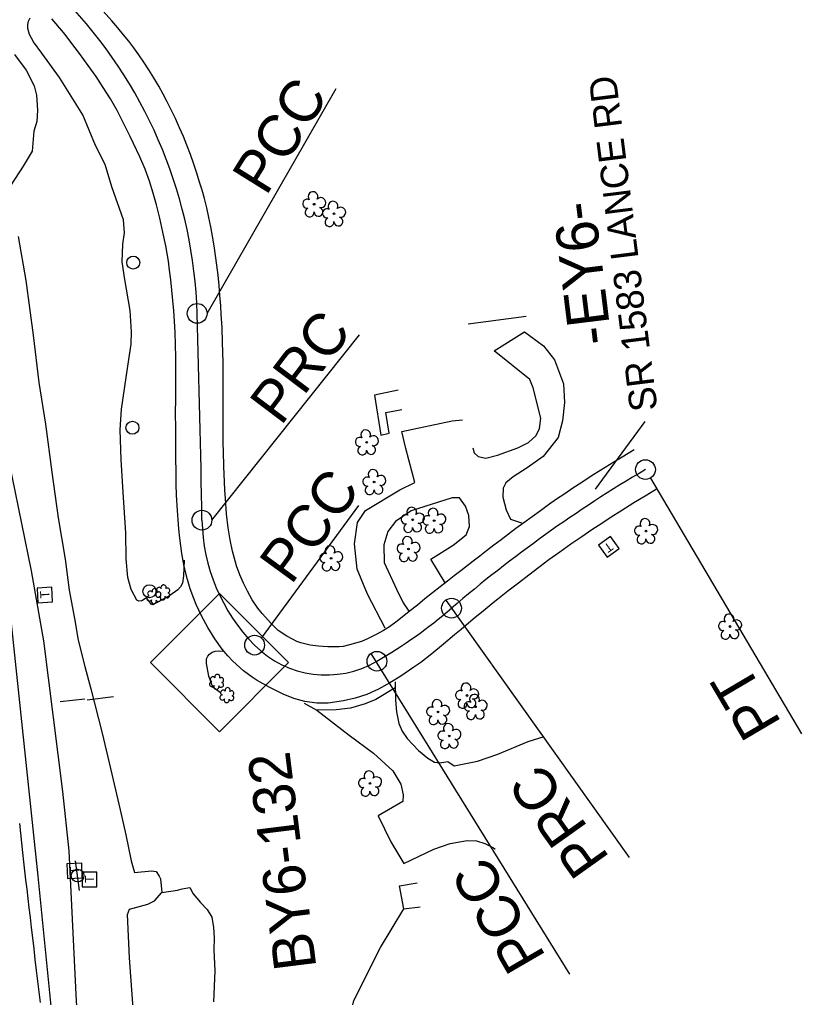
# Model space of a CAD drawing. Extents: x 476627 to 479509, y 495837 to 499842.
# Drawn here: x 478160.5 to 478457.3, y 497245.6 to 497616.9 of the extents above; entities that cross this region are included whole.
import ezdxf

# ---------------------------------------------------------------- set-up
doc = ezdxf.new("R2010")
doc.units = 0
for name, color, linetype in [('CTL Secondary Horizontal and Vertical CELL', 7, 'Continuous'), ('CTL Secondary Horizontal and Vertical Text', 7, 'Continuous'), ('Exist Horizontal Alignment', 7, 'Continuous'), ('Exist Horizontal Alignment Direction Label', 7, 'Continuous'), ('Exist Other Culture Area Outline', 7, 'Continuous'), ('Exist Other Culture Fence Line', 7, 'Continuous'), ('Exist Other Culture Sign', 7, 'Continuous'), ('Exist Roads Change in Surface', 7, 'Continuous'), ('Exist Roads EOP', 7, 'Continuous'), ('Exist Roads EOP Leader', 7, 'Continuous'), ('Exist Roads EOP Other', 7, 'Continuous'), ('Exist Roads EOP Text', 7, 'Continuous'), ('Exist Roads Soil', 7, 'Continuous'), ('Exist Utilities Other Pole CELL', 7, 'Continuous'), ('Exist Utilities Telephone Pedestal CELL', 7, 'Continuous'), ('Exist Utilities Telephone Pole CELL', 7, 'Continuous'), ('Exist Vegetation Hedge Row', 7, 'Continuous'), ('Exist Vegetation Shrub CELL', 7, 'Continuous'), ('Exist Vegetation Tree CELL', 7, 'Continuous'), ('Exist Vegetation Woods Line', 7, 'Continuous')]:
    doc.layers.add(name, color=color, linetype=linetype)

msp = doc.modelspace()

# ---------------------------------------------------------------- linework, layer by layer
at = {"layer": 'CTL Secondary Horizontal and Vertical CELL'}
msp.add_line((478236.26, 497372.67), (478236.26, 497372.67), dxfattribs=at)
msp.add_lwpolyline([(478210.19, 497372.76), (478236.4, 497398.97), (478262.65, 497372.72), (478236.44, 497346.51)], close=True, dxfattribs=at)
at = {"layer": 'Exist Horizontal Alignment'}
for p, q in [((478231.67, 497505.32), (478280.69, 497590.74)), ((478233.5, 497426.81), (478289.48, 497497.25)), ((478399.98, 497442.81), (478457.27, 497345.73)), ((478252.4, 497382), (478289.29, 497432.37)), ((478322.28, 497396.46), (478391.92, 497298.69)), ((478293.89, 497376.24), (478369.22, 497254.38))]:
    msp.add_line(p, q, dxfattribs=at)
for centre in [(478227.92, 497505.32), (478398.07, 497446.04), (478229.75, 497426.81), (478324.46, 497393.4), (478249.74, 497379.37), (478296.17, 497373.26)]:
    msp.add_circle(centre, 3.75, dxfattribs=at)
for centre, radius, start, end in [((478049.09, 497499.96), 178.91, 1.7193, 42.703), ((472276.25, 497326.67), 5954.35, 0.96365, 1.719327), ((478660.76, 497000.88), 516.89, 120.545, 130.5894), ((478298.83, 497427.98), 69.09, 180.9636, 224.7163), ((478198.36, 497540.58), 193.81, 300.3104, 310.5894), ((478276.89, 497406.25), 38.21, 224.7163, 300.3104)]:
    msp.add_arc(centre, radius, start, end, dxfattribs=at)
at = {"layer": 'Exist Other Culture Area Outline'}
msp.add_lwpolyline([(478304.26, 497476.19), (478295.26, 497474.27), (478297.62, 497459.04), (478300.85, 497459.8), (478299.55, 497467.66), (478305.58, 497468.87)], dxfattribs=at)
at = {"layer": 'Exist Other Culture Fence Line'}
msp.add_lwpolyline([(478330.72, 497501.4), (478352.74, 497504.27)], dxfattribs=at)
at = {"layer": 'Exist Other Culture Sign'}
for p, q in [((478185.28, 497358.89), (478175.93, 497357.87)), ((478196.2, 497359.72), (478186.14, 497358.48))]:
    msp.add_line(p, q, dxfattribs=at)
at = {"layer": 'Exist Roads Change in Surface'}
msp.add_lwpolyline([(478303.11, 497363.12), (478295.78, 497358.73), (478291.69, 497357.04), (478286.18, 497355.42), (478280.68, 497354.79), (478273.3, 497354.64)], dxfattribs=at)
at = {"layer": 'Exist Roads EOP'}
for points in [[(478393.82, 497453.5), (478389.2, 497450.74), (478386.12, 497448.87), (478381.17, 497445.83), (478377.52, 497443.52), (478373.88, 497441.16), (478370.55, 497438.97), (478367.41, 497436.87), (478364.36, 497434.78), (478361.3, 497432.65), (478358.18, 497430.42), (478355.03, 497428.13), (478351.92, 497425.84), (478348.91, 497423.62), (478346.08, 497421.49), (478343.32, 497419.41), (478340.53, 497417.29), (478337.78, 497415.2), (478335.15, 497413.19), (478332.64, 497411.26), (478327.95, 497407.6), (478325.5, 497405.71), (478322.9, 497403.69), (478320.1, 497401.47), (478317.22, 497399.18), (478314.38, 497396.92), (478311.49, 497394.6), (478308.44, 497392.14), (478303.79, 497388.41), (478300.91, 497386.29), (478298.64, 497384.87), (478296.15, 497383.55), (478292.8, 497381.9), (478290.27, 497380.8), (478285.8, 497379.42), (478283.34, 497378.89), (478281.77, 497378.72), (478277.54, 497378.7), (478274.02, 497378.94), (478270.86, 497379.34), (478267.33, 497380.24), (478265.77, 497380.79), (478264.09, 497381.59), (478261.93, 497382.8), (478258.72, 497384.88), (478256.15, 497387.4), (478252.56, 497391.4), (478250.93, 497393.38), (478248.74, 497396.6), (478246.97, 497399.81), (478245.45, 497402.96), (478244.12, 497406.06), (478242.91, 497409.43), (478241.38, 497415.11), (478240.48, 497419.3), (478239.7, 497423.97), (478239.1, 497429.17), (478238.66, 497435.07), (478238.46, 497438.27), (478238.28, 497441.41), (478238.05, 497447.17), (478237.9, 497452.89), (478237.82, 497456.03), (478237.78, 497459.33), (478237.76, 497462.81), (478237.79, 497466.51), (478237.83, 497472.45), (478237.82, 497476.6), (478237.79, 497480.7), (478237.73, 497486.69), (478237.67, 497490.61), (478237.6, 497494.24), (478237.4, 497499.96), (478237.07, 497504.85), (478236.85, 497508.24), (478236.58, 497512.07), (478236.25, 497515.96), (478235.87, 497519.84), (478235.43, 497523.61), (478234.93, 497527.33), (478234.38, 497531.03), (478233.77, 497534.67), (478233.12, 497538.18), (478232.39, 497541.7), (478231.54, 497545.35), (478230.65, 497548.9), (478229.79, 497552.1), (478228.87, 497555.22), (478227.81, 497558.54), (478226.64, 497562.04), (478225.36, 497565.66), (478224.04, 497569.23), (478222.7, 497572.52), (478221.27, 497575.8), (478219.66, 497579.28), (478218.05, 497582.68), (478216.57, 497585.67), (478215.07, 497588.56), (478213.35, 497591.67), (478211.51, 497594.81), (478209.63, 497597.8), (478207.72, 497600.67), (478205.79, 497603.48), (478203.87, 497606.16), (478201.96, 497608.67), (478199.96, 497611.16), (478197.76, 497613.81), (478195.57, 497616.38), (478192.3, 497620.11)], [(478402.32, 497438.59), (478398.56, 497436.33), (478393.64, 497433.34), (478388.7, 497430.29), (478385.06, 497427.98), (478381.45, 497425.6), (478377.75, 497423.11), (478373.86, 497420.49), (478369.8, 497417.7), (478365.59, 497414.73), (478361.45, 497411.73), (478357.6, 497408.85), (478353.82, 497405.97), (478349.84, 497402.93), (478345.86, 497399.84), (478342.07, 497396.81), (478340.29, 497395.37), (478337.2, 497392.87), (478332.69, 497389.22), (478328.11, 497385.36), (478325.6, 497383.23), (478321.43, 497379.72), (478317, 497376.07), (478312.78, 497372.83), (478310.15, 497370.94), (478305.26, 497367.59), (478301.05, 497364.99), (478296.69, 497362.64), (478292.3, 497360.68), (478287.89, 497359.22), (478283.44, 497358.19), (478277.66, 497357.37), (478273.3, 497357.37), (478268.83, 497357.93), (478264.67, 497359.06), (478260.53, 497360.71), (478255.5, 497363.23), (478250.73, 497365.98), (478248.75, 497367.25), (478245.55, 497369.56), (478241.46, 497373.28), (478239.54, 497375.3), (478237.45, 497377.87), (478234.65, 497381.78), (478231.97, 497386.09), (478229.57, 497390.55), (478227.57, 497394.84), (478226.68, 497397.05), (478225.31, 497400.71), (478224.2, 497404.32), (478223.01, 497409.21), (478222.11, 497414.13), (478221.37, 497419.96), (478221, 497423.51), (478220.69, 497426.95), (478220.44, 497430.47), (478220.14, 497436.29), (478220, 497440.55), (478219.92, 497445.17), (478219.86, 497450.3), (478219.82, 497455.93), (478219.79, 497461.67), (478219.76, 497467.43), (478219.79, 497472.95), (478219.86, 497478.23), (478219.87, 497483.44), (478219.8, 497488.57), (478219.69, 497493.46), (478219.54, 497498.07), (478219.32, 497502.35), (478219.02, 497506.33), (478218.67, 497510.26), (478218.28, 497514.18), (478217.87, 497518.04), (478217.44, 497521.79), (478216.99, 497525.17), (478216.01, 497530.95), (478214.93, 497536.21), (478213.7, 497541.55), (478212.45, 497546.61), (478211.17, 497551.04), (478209.77, 497555.5), (478208.15, 497560.06), (478206.17, 497564.72), (478203.82, 497569.81), (478202.5, 497572.54), (478199.87, 497577.86), (478197.52, 497582.4), (478195, 497586.77), (478192.28, 497591.12), (478189.58, 497595.24), (478186.55, 497599.5), (478183.21, 497604), (478179.98, 497608.31), (478177.8, 497611.18), (478174.34, 497615.4), (478172.82, 497617.23)], [(478160.43, 497311.6), (478160.83, 497307.97), (478161.24, 497304.24), (478161.64, 497300.61), (478162.04, 497297.07), (478162.43, 497293.63), (478162.82, 497290.21), (478163.22, 497286.73), (478163.63, 497283.2), (478164.05, 497279.62), (478164.48, 497275.94), (478164.93, 497272.12), (478165.4, 497268.18), (478165.88, 497264.11), (478166.37, 497259.97), (478166.86, 497255.86), (478167.34, 497251.77), (478167.81, 497247.69), (478168.29, 497243.63)]]:
    msp.add_lwpolyline(points, dxfattribs=at)
at = {"layer": 'Exist Roads EOP Leader'}
msp.add_line((478379.15, 497438.63), (478397.9, 497464.22), dxfattribs=at)
at = {"layer": 'Exist Roads EOP Other'}
for points in [[(478222.93, 497411.63), (478222.68, 497405.72), (478222.36, 497402.94), (478221.66, 497401.5), (478220.57, 497400.41), (478217.52, 497398.26), (478211.09, 497394.64), (478210.56, 497394.8), (478208.65, 497397.29), (478206.98, 497396.24), (478205.78, 497396.02), (478205.05, 497396.39), (478202.91, 497400.49), (478201.59, 497405.04), (478201.01, 497412.18), (478200.79, 497422.07), (478199.82, 497437.28), (478199.08, 497449.8), (478198.76, 497461.08), (478199.22, 497468.97), (478201.66, 497485.25), (478202.82, 497493.61), (478202.97, 497498.33), (478202.44, 497506.49), (478200.53, 497518.23), (478199.48, 497524.91), (478199.69, 497531.57), (478200.29, 497535.86), (478200, 497540.89), (478195.54, 497553.4), (478192.97, 497561.85), (478189.33, 497569.13), (478184.48, 497580.67), (478175.67, 497594.94), (478169.03, 497604.12), (478165.76, 497608.41), (478164.3, 497611.2), (478163.68, 497613.49), (478163.6, 497614.97), (478163.88, 497616.28), (478164.6, 497617.61)], [(478158.58, 497603.6), (478163.02, 497597.72), (478166, 497591.76), (478167, 497588.13), (478167.37, 497582.54), (478167.08, 497578.21), (478165.96, 497574.54), (478165.31, 497566.92), (478161.85, 497561.27), (478157.25, 497553.99)], [(478159.97, 497534.58), (478162.89, 497517.88), (478165.68, 497497.05), (478167.84, 497479.11), (478170.36, 497463.26), (478172.76, 497445.1), (478175.16, 497427.69), (478177.82, 497412.02), (478179.39, 497400.26), (478181.42, 497389.44), (478182.81, 497381.27), (478185.26, 497371.23), (478187.57, 497362.81), (478191.86, 497345.91), (478195.51, 497330.36), (478198.74, 497316.77), (478200.79, 497307.33), (478202.83, 497297.44), (478204.09, 497293), (478210.61, 497293.7), (478212.34, 497293.36), (478213.54, 497291.67), (478214.02, 497290.57), (478214.52, 497285.39), (478220.43, 497286.38), (478222.27, 497286.78), (478225.14, 497287.4), (478226.36, 497284.94), (478229.16, 497281.61), (478231.67, 497279.04), (478233.53, 497276.02), (478234.13, 497272.18), (478234.37, 497268.18), (478234.29, 497263.69), (478234.58, 497255.76), (478234.09, 497243.91)], [(478236.81, 497361.26), (478233.85, 497363.41), (478232.33, 497367.62), (478231.51, 497372.36), (478231.5, 497374.22), (478231.99, 497375.14), (478232.63, 497375.91), (478233.6, 497376.69), (478234.75, 497377.06), (478235.95, 497377.21), (478237.68, 497377.12)], [(478303.04, 497365.39), (478303.26, 497358.53), (478303.63, 497354.09), (478304.42, 497349.58), (478305.75, 497346.73), (478307.66, 497343.97), (478311.95, 497339.39), (478315.45, 497336.46), (478318.06, 497334.88), (478320.02, 497334.63), (478323.01, 497335.12), (478325.41, 497333.54), (478334.36, 497335.29), (478342.05, 497337.92), (478353.52, 497342.84), (478359.65, 497344.63)], [(478268.5, 497357.36), (478273.3, 497354.64), (478285.57, 497345.16), (478294.91, 497338.38), (478302.24, 497331.68), (478305.19, 497326.53), (478306.15, 497322.49), (478306.02, 497319.96), (478296.65, 497314.5), (478301.4, 497304.7), (478306.35, 497296.41), (478317.7, 497301.86), (478324.01, 497304.07), (478330.4, 497305.18), (478333.88, 497305.06), (478337.05, 497304), (478340.36, 497302.46), (478341.03, 497301.86)]]:
    msp.add_lwpolyline(points, dxfattribs=at)
at = {"layer": 'Exist Roads Soil'}
for points in [[(478332.59, 497454.26), (478333, 497452.35), (478334.6, 497451.03), (478337.54, 497450.37), (478341.93, 497451.44), (478349.57, 497454.29), (478353.66, 497456.25), (478356.59, 497458.91), (478357.83, 497461.67), (478358.3, 497465.52), (478355.42, 497477.07), (478354.13, 497480.29), (478340.61, 497491.08), (478352.22, 497498.35), (478359.43, 497493.03), (478363.5, 497487.74), (478366.91, 497478.62), (478367.39, 497471.48), (478366.53, 497464.52), (478364.89, 497458.16), (478359.27, 497450.94), (478353.14, 497446.63), (478347.81, 497443.28), (478345.09, 497441.02), (478344.1, 497439.02), (478343.98, 497435.49), (478345.26, 497430.72), (478346.85, 497427.21), (478351.39, 497425.72)], [(478299.25, 497385.83), (478292.59, 497398.7), (478288.68, 497408.19), (478287.58, 497417.87), (478288.73, 497425.96), (478291.8, 497430.43), (478304.8, 497438.37), (478310.49, 497441.15), (478307.1, 497454.02), (478305.63, 497460.47), (478324.66, 497464.49), (478328.63, 497464.89)], [(478322.11, 497403.06), (478316.61, 497411.96), (478325.07, 497417.31), (478329.97, 497421.23), (478331.23, 497424.47), (478331.06, 497428.54), (478329.8, 497432.12), (478327.49, 497435.36), (478324.71, 497435.29), (478309.14, 497430.42), (478303.16, 497426.26), (478300.28, 497422.55), (478298.73, 497417.4), (478298.92, 497410.79), (478303.64, 497400.59), (478306.14, 497395.37), (478308.25, 497392.27)], [(478232.9, 497234.19), (478229.08, 497241.38), (478227.08, 497242.13), (478203.69, 497241.5), (478202.19, 497260.65), (478201.46, 497277.13), (478202.27, 497279.15), (478209.18, 497280.95), (478211.76, 497282.22), (478214.52, 497285.39)]]:
    msp.add_lwpolyline(points, dxfattribs=at)
at = {"layer": 'Exist Utilities Other Pole CELL'}
for centre in [(478203.66, 497524.61), (478203.37, 497461.91), (478209.82, 497399.83)]:
    msp.add_circle(centre, 2.46, dxfattribs=at)
at = {"layer": 'Exist Utilities Telephone Pedestal CELL'}
for p, q in [((478384.27, 497416.67), (478384.27, 497416.67)), ((478170.09, 497398.3), (478170.09, 497398.3)), ((478181.4, 497293.6), (478181.4, 497293.6)), ((478187.04, 497290.26), (478187.04, 497290.26))]:
    msp.add_line(p, q, dxfattribs=at)
for points in [[(478384.85, 497420.56), (478380.29, 497417.31), (478383.54, 497412.75), (478388.09, 497416), (478384.85, 497420.56)], [(478173.08, 497395.76), (478172.72, 497401.34), (478167.14, 497400.99), (478167.5, 497395.41), (478173.08, 497395.76)], [(478184.32, 497290.98), (478184.11, 497296.57), (478178.52, 497296.36), (478178.73, 497290.77), (478184.32, 497290.98)], [(478189.86, 497287.54), (478189.86, 497293.13), (478184.27, 497293.13), (478184.27, 497287.54), (478189.86, 497287.54)]]:
    msp.add_lwpolyline(points, dxfattribs=at)
at = {"layer": 'Exist Utilities Telephone Pole CELL'}
for p, q in [((478183.31, 497286.24), (478181.79, 497297.48)), ((478182.55, 497291.87), (478182.55, 497291.87))]:
    msp.add_line(p, q, dxfattribs=at)
msp.add_circle((478182.55, 497291.87), 2.41, dxfattribs=at)
at = {"layer": 'Exist Vegetation Hedge Row'}
for points in [[(478190.09, 497080.94), (478179.04, 497176.49), (478167.62, 497291.69), (478149.68, 497459.52), (478153.94, 497461.52), (478164.92, 497407.53), (478169.64, 497380.94), (478176.79, 497323.8), (478179.27, 497301.23), (478182, 497244.2), (478186.73, 497178.82), (478185.59, 497158.67), (478193.35, 497075.53), (478190.09, 497080.94)], [(478306.34, 497279.2), (478304.78, 497288.01), (478311.4, 497289.14)]]:
    msp.add_lwpolyline(points, dxfattribs=at)
at = {"layer": 'Exist Vegetation Shrub CELL'}
for p, q in [((478211.59, 497397.78), (478211.59, 497397.78)), ((478214.95, 497399.22), (478214.95, 497399.22)), ((478235.36, 497365.23), (478235.36, 497365.23)), ((478239.25, 497360.2), (478239.25, 497360.2))]:
    msp.add_line(p, q, dxfattribs=at)
for centre, radius, start, end in [((478210.1, 497398.9), 0.968, 35.8908, 245.4216), ((478211.81, 497399.82), 0.99, 334.8391, 200.4717), ((478213.47, 497400.35), 0.968, 35.8908, 245.4216), ((478215.18, 497401.26), 0.99, 334.8391, 200.4717), ((478216.63, 497400.09), 0.929, 284.4567, 126.0861), ((478209.79, 497397.07), 0.955, 95.1099, 327.9534), ((478211.46, 497396.09), 0.984, 151.2797, 21.387), ((478213.15, 497398.52), 0.955, 95.1099, 327.9534), ((478213.22, 497396.85), 0.937, 204.9913, 73.4601), ((478213.26, 497398.65), 0.929, 284.4567, 126.0861), ((478214.83, 497397.54), 0.984, 151.2797, 21.387), ((478216.59, 497398.29), 0.937, 204.9913, 73.4601), ((478233.88, 497366.36), 0.968, 35.8908, 245.4216), ((478235.59, 497367.27), 0.99, 334.8391, 200.4717), ((478237.04, 497366.1), 0.929, 284.4567, 126.0861), ((478233.56, 497364.53), 0.955, 95.1099, 327.9534), ((478235.24, 497363.55), 0.984, 151.2797, 21.387), ((478237, 497364.3), 0.937, 204.9913, 73.4601), ((478239.48, 497362.24), 0.99, 334.8391, 200.4717), ((478237.45, 497359.49), 0.955, 95.1099, 327.9534), ((478237.77, 497361.32), 0.968, 35.8908, 245.4216), ((478239.12, 497358.51), 0.984, 151.2797, 21.387), ((478240.89, 497359.27), 0.937, 204.9913, 73.4601), ((478240.92, 497361.06), 0.929, 284.4567, 126.0861)]:
    msp.add_arc(centre, radius, start, end, dxfattribs=at)
at = {"layer": 'Exist Vegetation Tree CELL'}
for p, q in [((478272.29, 497546.79), (478272.29, 497546.79)), ((478279.86, 497543.15), (478279.86, 497543.15)), ((478292.27, 497456.39), (478292.27, 497456.39)), ((478295.08, 497441.32), (478295.08, 497441.32)), ((478309.72, 497426.98), (478309.72, 497426.98)), ((478317.87, 497426.62), (478317.87, 497426.62)), ((478398.26, 497422.67), (478398.26, 497422.67)), ((478308.1, 497415.88), (478308.1, 497415.88)), ((478278.75, 497412.34), (478278.75, 497412.34)), ((478430.15, 497386.45), (478430.15, 497386.45)), ((478330.33, 497360.24), (478330.33, 497360.24)), ((478333.56, 497355.95), (478333.56, 497355.95)), ((478319.32, 497353.98), (478319.32, 497353.98)), ((478323.62, 497344.88), (478323.62, 497344.88)), ((478293.5, 497326.86), (478293.5, 497326.86))]:
    msp.add_line(p, q, dxfattribs=at)
for centre in [(478272.29, 497546.79), (478279.86, 497543.15), (478292.27, 497456.39), (478295.08, 497441.32), (478309.72, 497426.98), (478317.87, 497426.62), (478398.26, 497422.67), (478308.1, 497415.88), (478278.75, 497412.34), (478430.15, 497386.45), (478330.33, 497360.24), (478333.56, 497355.95), (478319.32, 497353.98), (478323.62, 497344.88), (478293.5, 497326.86)]:
    msp.add_circle(centre, 0.326, dxfattribs=at)
for centre, radius, start, end in [((478269.69, 497546.95), 1.73, 62.6636, 279.3457), ((478271.91, 497549.67), 1.86, 330.1651, 219.7134), ((478274.84, 497547.38), 1.9, 257.1011, 134.1999), ((478270.59, 497543.67), 1.69, 111.5671, 6.231), ((478273.97, 497543.89), 1.7, 181.2822, 74.56), ((478277.25, 497543.31), 1.73, 62.6636, 279.3457), ((478279.47, 497546.03), 1.86, 330.1651, 219.7134), ((478282.41, 497543.74), 1.9, 257.1011, 134.1999), ((478278.15, 497540.03), 1.69, 111.5671, 6.231), ((478281.53, 497540.25), 1.7, 181.2822, 74.56), ((478291.89, 497459.26), 1.86, 330.1651, 219.7134), ((478289.67, 497456.54), 1.73, 62.6636, 279.3457), ((478294.82, 497456.98), 1.9, 257.1011, 134.1999), ((478290.57, 497453.27), 1.69, 111.5671, 6.231), ((478293.94, 497453.49), 1.7, 181.2822, 74.56), ((478294.69, 497444.19), 1.86, 330.1651, 219.7134), ((478292.47, 497441.47), 1.73, 62.6636, 279.3457), ((478297.63, 497441.91), 1.9, 257.1011, 134.1999), ((478293.37, 497438.2), 1.69, 111.5671, 6.231), ((478296.75, 497438.42), 1.7, 181.2822, 74.56), ((478309.34, 497429.86), 1.86, 330.1651, 219.7134), ((478312.27, 497427.57), 1.9, 257.1011, 134.1999), ((478317.49, 497429.49), 1.86, 330.1651, 219.7134), ((478307.12, 497427.14), 1.73, 62.6636, 279.3457), ((478311.39, 497424.08), 1.7, 181.2822, 74.56), ((478315.27, 497426.77), 1.73, 62.6636, 279.3457), ((478320.42, 497427.21), 1.9, 257.1011, 134.1999), ((478397.88, 497425.54), 1.86, 330.1651, 219.7134), ((478308.02, 497423.86), 1.69, 111.5671, 6.231), ((478316.17, 497423.5), 1.69, 111.5671, 6.231), ((478319.54, 497423.72), 1.7, 181.2822, 74.56), ((478395.66, 497422.83), 1.73, 62.6636, 279.3457), ((478400.81, 497423.26), 1.9, 257.1011, 134.1999), ((478307.72, 497418.75), 1.86, 330.1651, 219.7134), ((478310.65, 497416.47), 1.9, 257.1011, 134.1999), ((478396.56, 497419.55), 1.69, 111.5671, 6.231), ((478399.94, 497419.77), 1.7, 181.2822, 74.56), ((478278.37, 497415.21), 1.86, 330.1651, 219.7134), ((478281.3, 497412.93), 1.9, 257.1011, 134.1999), ((478305.49, 497416.03), 1.73, 62.6636, 279.3457), ((478309.77, 497412.98), 1.7, 181.2822, 74.56), ((478276.15, 497412.49), 1.73, 62.6636, 279.3457), ((478277.05, 497409.22), 1.69, 111.5671, 6.231), ((478280.42, 497409.44), 1.7, 181.2822, 74.56), ((478306.4, 497412.76), 1.69, 111.5671, 6.231), ((478429.77, 497389.33), 1.86, 330.1651, 219.7134), ((478432.7, 497387.04), 1.9, 257.1011, 134.1999), ((478427.55, 497386.61), 1.73, 62.6636, 279.3457), ((478428.45, 497383.33), 1.69, 111.5671, 6.231), ((478431.83, 497383.55), 1.7, 181.2822, 74.56), ((478329.94, 497363.11), 1.86, 330.1651, 219.7134), ((478332.87, 497360.82), 1.9, 257.1011, 134.1999), ((478327.72, 497360.39), 1.73, 62.6636, 279.3457), ((478332, 497357.34), 1.7, 181.2822, 74.56), ((478333.18, 497358.83), 1.86, 330.1651, 219.7134), ((478316.71, 497354.14), 1.73, 62.6636, 279.3457), ((478318.93, 497356.86), 1.86, 330.1651, 219.7134), ((478321.87, 497354.57), 1.9, 257.1011, 134.1999), ((478328.62, 497357.12), 1.69, 111.5671, 6.231), ((478330.96, 497356.11), 1.73, 62.6636, 279.3457), ((478336.11, 497356.54), 1.9, 257.1011, 134.1999), ((478317.61, 497350.86), 1.69, 111.5671, 6.231), ((478320.99, 497351.08), 1.7, 181.2822, 74.56), ((478331.86, 497352.83), 1.69, 111.5671, 6.231), ((478335.23, 497353.05), 1.7, 181.2822, 74.56), ((478323.23, 497347.75), 1.86, 330.1651, 219.7134), ((478321.01, 497345.03), 1.73, 62.6636, 279.3457), ((478326.16, 497345.47), 1.9, 257.1011, 134.1999), ((478321.91, 497341.76), 1.69, 111.5671, 6.231), ((478325.29, 497341.98), 1.7, 181.2822, 74.56), ((478293.11, 497329.73), 1.86, 330.1651, 219.7134), ((478296.05, 497327.45), 1.9, 257.1011, 134.1999), ((478290.89, 497327.01), 1.73, 62.6636, 279.3457), ((478295.17, 497323.96), 1.7, 181.2822, 74.56), ((478291.8, 497323.74), 1.69, 111.5671, 6.231)]:
    msp.add_arc(centre, radius, start, end, dxfattribs=at)
at = {"layer": 'Exist Vegetation Woods Line'}
msp.add_lwpolyline([(478273.28, 497186.57), (478287.42, 497244.42), (478297.46, 497264.61), (478306.34, 497279.2), (478312.52, 497280.03)], dxfattribs=at)

# ---------------------------------------------------------------- texts
at = {"layer": 'CTL Secondary Horizontal and Vertical Text'}
msp.add_text('BY6-132', height=16, rotation=97.1248, dxfattribs=at).set_placement((478273.23, 497256.93))
at = {"layer": 'Exist Horizontal Alignment'}
for s, rotation, p in [('PCC', 58.0995, (478254.08, 497549.6)), ('PRC', 52.9272, (478259.73, 497462.31)), ('PCC', 53.8468, (478263.58, 497401.9)), ('PT', 120.545, (478449.9, 497349.8)), ('PRC', 125.4597, (478384.77, 497298.54)), ('PCC', 120.185, (478360.5, 497261.07))]:
    msp.add_text(s, height=16, rotation=rotation, dxfattribs=at).set_placement(p)
at = {"layer": 'Exist Horizontal Alignment Direction Label'}
msp.add_text('-EY6-', height=16, rotation=96.9963, dxfattribs=at).set_placement((478385.32, 497494.19))
at = {"layer": 'Exist Roads EOP Text'}
msp.add_text('SR 1583 LANCE RD', height=10.4, rotation=97.1247, dxfattribs=at).set_placement((478402.67, 497468.8))
at = {"layer": 'Exist Utilities Telephone Pedestal CELL'}
for rotation, p in [(215.4788, (478384.19, 497418.73)), (93.6475, (478171.87, 497397.28)), (92.1886, (478183.15, 497292.53)), (90, (478188.75, 497289.13))]:
    msp.add_text('T', height=3.42, rotation=rotation, dxfattribs=at).set_placement(p)

doc.saveas('drawing.dxf')
